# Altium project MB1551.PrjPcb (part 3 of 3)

## Sheet USB_TYPEC.SchDoc: USB TYPE C
size A3; Date: Not used; ApprovedBy: Not used; CheckedBy: Not used; Author: Not used; CompanyName: STMicroelectronics; DrawnBy: Not used; Engineer: Not used; Organization: Not used; Address1: Not used; Address2: Not used; Address3: Not used; Address4: Not used; DocumentNumber: 9; Revision: Not used; SheetNumber: 9; SheetTotal: 16
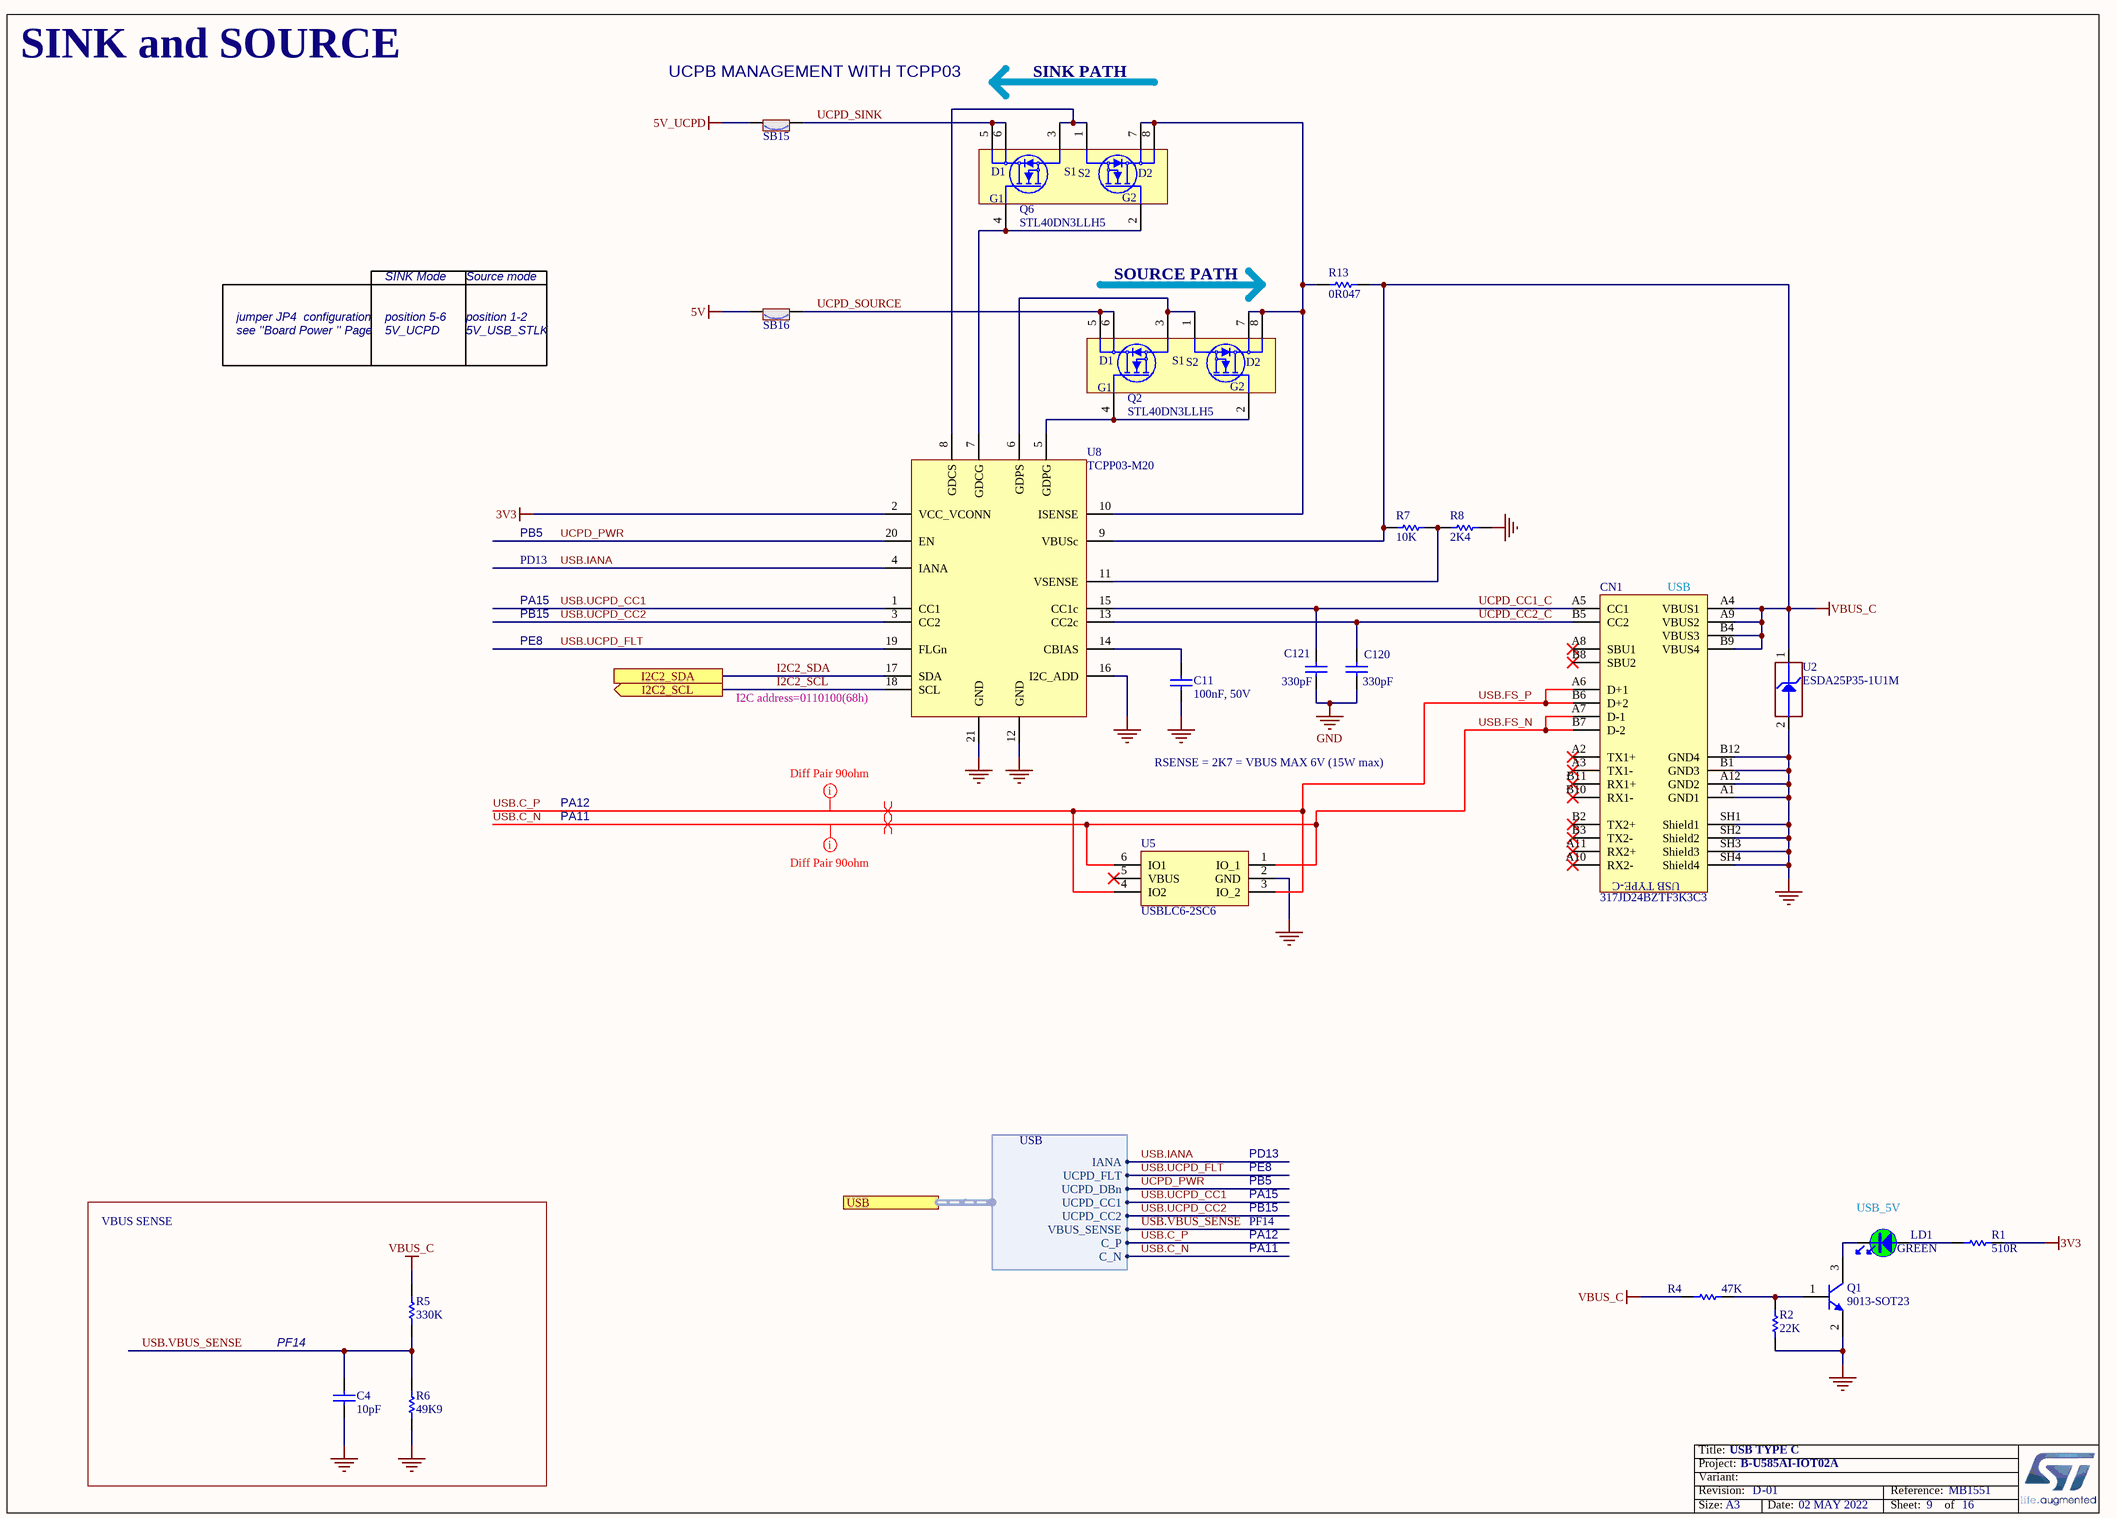
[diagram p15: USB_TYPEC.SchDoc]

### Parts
C4  value 10pF  [C0603]
C11  value 100nF, 50V  [C0603]
C120  value 330pF  [C0402]  (hidden comment: Capacitor)
C121  value 330pF  [C0402]  (hidden comment: Capacitor)
CN1  value 317JD24BZTF3K3C3  [CON_USB-TYPEC_COXOC_317JD24BZTF3K3C3]  (hidden comment: USB_TYPE_C_Receptacle_317JD24BZTF3K3C3)
LD1  value GREEN  [LED_0603_GREEN]
Q1  value 9013-SOT23  [NPN_SOT23]
Q2  STL40DN3LLH5  [PowerFLAT_5x6]
Q6  STL40DN3LLH5  [PowerFLAT_5x6]
R1  value 510R  [R0603]
R2  value 22K  [R0603]
R4  value 47K  [R0603]
R5  value 330K  [R0603]
R6  value 49K9  [R0603]
R7  value 10K  [R0603]
R8  value 2K4  [R0402]  (hidden comment: Resistor)
R13  value 0R047  [R0805_H0P5]  (hidden comment: Resistor)
SB15  (no value)  [SOLDER-BRIDGE_R0603-0R]
SB16  (no value)  [SOLDER-BRIDGE_R0603-0R]
U2  value ESDA25P35-1U1M  [ESD_QFN1610_2N_1K_2A]  (hidden comment: ESD-TRANSIL)
U5  USBLC6-2SC6  [ESD_SOT23-6L]
U8  TCPP03-M20  [ICC_QFN20-EPAD_4X4_P050]

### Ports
I2C2_SCL (out), I2C2_SDA, USB (harness USB)

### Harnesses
USB: UCPD_FLT, UCPD_DBn, UCPD_CC2, VBUS_SENSE, C_P, C_N, UCPD_CC1, IANA

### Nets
3V3: R1.1 U8.2(VCC_VCONN)
5V: SB16.2
5V_UCPD: SB15.2
GND: C4.1 C11.2 C120.1 C121.1 CN1.A1(GND1) CN1.A12(GND2) CN1.B1(GND3) CN1.B12(GND4) CN1.SH1(Shield1) CN1.SH2(Shield2) CN1.SH3(Shield3) CN1.SH4(Shield4) Q1.2(E) R2.1 R6.1 R8.2 U2.2(GND) U5.2(GND) U8.12(GND) U8.16(I2C_ADD) U8.21(GND)
VBUS_C: CN1.A4(VBUS1) CN1.A9(VBUS2) CN1.B4(VBUS3) CN1.B9(VBUS4) R4.1 R5.2 R7.2 R13.1 U2.1(IO1) U8.9(VBUSc)
I2C2_SCL: U8.18(SCL) ; port I2C2_SCL
I2C2_SDA: U8.17(SDA) ; port I2C2_SDA
UCPD_CC1_C: C121.2 CN1.A5(CC1) U8.15(CC1c)
UCPD_CC2_C: C120.2 CN1.B5(CC2) U8.13(CC2c)
UCPD_PWR: U8.20(EN) ; port USB.UCPD_DBn
UCPD_SINK: Q6.5(D1) Q6.6(D1) SB15.1
UCPD_SOURCE: Q2.5(D1) Q2.6(D1) SB16.1
USB.C_N: CN1.A7(D-1) CN1.B7(D-2) U5.1(IO_1) U5.6(IO1) ; port USB.C_N  [also labelled USB.FS_N]
USB.C_P: CN1.A6(D+1) CN1.B6(D+2) U5.3(IO_2) U5.4(IO2) ; port USB.C_P  [also labelled USB.FS_P]
USB.IANA: U8.4(IANA) ; port USB.IANA
USB.UCPD_CC1: U8.1(CC1) ; port USB.UCPD_CC1  [project net T.JTDI]
USB.UCPD_CC2: U8.3(CC2) ; port USB.UCPD_CC2
USB.UCPD_FLT: U8.19(FLGn) ; port USB.UCPD_FLT
USB.VBUS_SENSE: C4.2 R5.1 R6.2 ; port USB.VBUS_SENSE
NetC11_1: C11.1 U8.14(CBIAS)
NetLD1_1: LD1.1 R1.2
NetLD1_2: LD1.2 Q1.3(C)
NetQ1_1: Q1.1(B) R2.2 R4.2
NetQ2_1: Q2.1(S2) Q2.3(S1) U8.6(GDPS)
NetQ2_2: Q2.2(G2) Q2.4(G1) U8.5(GDPG)
NetQ2_7: Q2.7(D2) Q2.8(D2) Q6.7(D2) Q6.8(D2) R13.2 U8.10(ISENSE)
NetQ6_1: Q6.1(S2) Q6.3(S1) U8.8(GDCS)
NetQ6_2: Q6.2(G2) Q6.4(G1) U8.7(GDCG)
NetR7_1: R7.1 R8.1 U8.11(VSENSE)

Not connected (* = marked no-connect by the designer): CN1 A2(TX1+)* A3(TX1-)* A8(SBU1)* A10(RX2-)* A11(RX2+)* B2(TX2+)* B3(TX2-)* B8(SBU2)* B10(RX1-)* B11(RX1+)*; U5 5(VBUS)*

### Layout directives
mark named Diff Pair 90ohm: USB.C_N, USB.C_P
differential pair: USB.C_N, USB.C_P

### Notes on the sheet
- SINK and SOURCE
- (near SB15) UCPB MANAGEMENT WITH TCPP03
- SINK PATH
- jumper JP4  configuration
- position 5-6
- SINK Mode
- Source mode
- position 1-2
- SOURCE PATH
- see ''Board Power '' Page
- 5V_UCPD
- 5V_USB_STLK
- PB5
- PD13
- (near CN1) USB
- PA15
- PB15
- PE8
- (near U8) I2C address=0110100(68h)
- RSENSE = 2K7 = VBUS MAX 6V (15W max)
- PA12
- PA11
- VBUS SENSE
- PF14
- (near LD1) USB_5V

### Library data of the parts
C4 = MCD-00637: Capacitor, MLCC, 10pF, 50V, NPO, 5%, 0603, T=0,8mm; Manufacturer_Part_Number: CC0603JRNPO9BN100; Manufacturer: YAGEO; Provided_By: subcon; Initial_Board_Reference: MB1319
C11 = MCD-01099: Capacitor,100nF,50V,X7R,10%,0603; Manufacturer_Part_Number: CC0603KRX7R9BB104; Manufacturer: YAGEO; BMS_Part_Number: 9142278; Provided_By: SUBCO
C120 C121 = MCD-01579: Capacitor, MLCC, 330pF, 50V, NPO, +/-5%, 0402, T=0,5mm; Part_Preference: Recommended; Manufacturer: YAGEO; Manufacturer_Part_Number: CC0402JRNPO9BN331
CN1 = MCD-01108: USB tyce C certified receptacle for 1.6mm pcb height; Part_Type: Connector; Manufacturer: CHANT SINCERE (COXOC); Provided_By: SUBCO
LD1 = MCD-00050: LED, Green, 0603; Part_Type: Display; Manufacturer_Part_Number: 19-213SYGC/S530-E2/TR8; Manufacturer: EVERLIGHT; ECCN_US: EAR99; ECCN_EU: NEC; Provided_By: Subcon; Initial_Board_Reference: MB1274
Q1 = MCD-00073: NPN Bipolar Transistor; Part_Type: IC; Manufacturer_Part_Number: BSR14; Manufacturer: NXP; ECCN_US: EAR99; ECCN_EU: NEC; Provided_By: Subcon; Initial_Board_Reference: MB1274
Q2 Q6 = MCD-02152: Dual N-channel 30 V, 0.016 Ω typ., 40 A, STripFET™ H5 Power MOSFET; Part_Type: Transistor; Manufacturer: STMICROELECTRONICS; ECCN_US: EAR99; ECCN_EU: NEC; Provided_By: SUBCO
R1 = MCD-00225: Resistor,510R,0603,1%,1/10W; Manufacturer_Part_Number: RC0603FR-07510RL; Manufacturer: YAGEO; Provided_By: Subcon; Initial_Board_Reference: MB1319
R2 = MCD-00430: Resistor,22K,0603,1%,1/10W; Manufacturer_Part_Number: RC0603FR-0722KL; Manufacturer: YAGEO; Provided_By: Subcon
R4 = MCD-00222: Resistor,47K,0603,1%,1/10W; Manufacturer_Part_Number: RC0603FR-0747KL; Manufacturer: YAGEO; Provided_By: Subcon; Initial_Board_Reference: MB1319
R5 = MCD-00458: Resistor,330K,0603,1%,1/10W; Manufacturer_Part_Number: RC0603FR-07330KL; Manufacturer: YAGEO; Provided_By: Subcon
R6 = MCD-01171: Resistor,49K9,0603,1%; Manufacturer_Part_Number: RC0603FR-0749K9L; Manufacturer: YAGEO; Provided_By: Subcon; Initial_Board_Reference: MB1397
R7 = MCD-00220: Resistor,10K,0603,1%,1/10W; Manufacturer_Part_Number: RC0603FR-0710KL; Manufacturer: YAGEO; Provided_By: Subcon; Initial_Board_Reference: MB1319
R8 = MCD-00433: Resistor,2K4,0402,1%,1/16W; Part_Preference: Recommended; Manufacturer: YAGEO; Manufacturer_Part_Number: RC0402FR-072K4L
R13 = MCD-02151: Current Detection Resistor, 0R047, 0805, 1%, 1/4W; Manufacturer_Part_Number: RL0805FR-7W0R047L; Manufacturer: YAGEO; ECCN_US: NEC; ECCN_EU: EAR99; Provided_By: SUBCO
SB15 SB16 = MCD-00071: Solder Bridge ON; Part_Type: Mechanical; Provided_By: Subcon; Initial_Board_Reference: mb1274
U2 = MCD-01207: High power Transient voltage suppressor:25V/35A EOS and ESD transients protection.; Part_Type: Diode; Manufacturer: STMICROELECTRONICS; BMS_Part_Number: 9179045; ECCN_US: EAR99; ECCN_EU: NEC; Provided_By: SUBCO with ST control
U5 = MCD-00163: Very low capacitance ESD protection; Part_Type: IC; Manufacturer: STMICROELECTRONICS; BMS_Part_Number: 9151075; ECCN_US: EAR99; ECCN_EU: NEC; Provided_By: SUBCO with ST control
U8 = MCD-02130: USB Type-C Port Protection for USB DRP Power Delivery, PPS compliant; Part_Type: IC; Manufacturer: STMICROELECTRONICS; ECCN_US: EAR99; ECCN_EU: NEC; Provided_By: SUBCO with ST control

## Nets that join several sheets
2V8: BOARD_PWR (SB9.2 TP12.1), Camera (8 pins)
3V3: ARDUINO (CN17.2 CN17.4 R9.1), AUDIO (7 pins), BOARD_PWR (5 pins), Camera (R32.2), MCU_CLOCK_&_RESET (5 pins), MEMs (38 pins), OCTOSPI (SB2.1 SB8.1), STMod+ (8 pins), ST_LINK_V3E (CN9.3 CN10.1 R54.2), WIFI&BT (5 pins), USB_TYPEC (R1.1 U8.2)
5V: ARDUINO (CN17.5), BOARD_PWR (10 pins), STMod+ (CN2.6 CN2.15 CN3.6 CN3.15), ST_LINK_V3E (R57.1), USB_TYPEC (SB16.2)
5V_UCPD: BOARD_PWR (JP4.5), ST_LINK_V3E (D3.1), USB_TYPEC (SB15.2)
5V_USB_CHGR: BOARD_PWR (JP4.7), ST_LINK_V3E (8 pins)
5V_USB_STLK: BOARD_PWR (JP4.1), ST_LINK_V3E (C52.2 U18.1)
5V_VIN: ARDUINO (R63.2), BOARD_PWR (C116.2 JP4.3 U38.2 U38.4), ST_LINK_V3E (D2.1)
GND: ARDUINO (5 pins), AUDIO (7 pins), BOARD_PWR (13 pins), Camera (15 pins), MCU_CLOCK_&_RESET (14 pins), MCU_PWR (38 pins), Mechanical_Parts (H1.1 H3.1 H4.1), MEMs (42 pins), OCTOSPI (15 pins), STMod+ (10 pins), ST_LINK_V3E (101 pins), WIFI&BT (42 pins), USB_TYPEC (21 pins)
VDD_MCU: BOARD_PWR (JP3.1), MCU_IO (R27.1 R28.1 R59.1 R60.1), MCU_PWR (37 pins)
VIN: ARDUINO (CN17.8), BOARD_PWR (C117.2 U38.3)
VREFP: ARDUINO (C74.1 R47.2), MCU_PWR (C38.1 C39.2 R21.2 U13.L1)
ARD.D0_RX: ARDUINO (CN14.1), MCU_IO (U13.L13), STMod+ (U3.7)
ARD.D1_TX: ARDUINO (CN14.2), MCU_IO (U13.L12), STMod+ (U3.4)
ARD.D2_IO: ARDUINO (CN14.3), MCU_IO (U13.J11)
ARD.D3_TIM: ARDUINO (CN14.4), MCU_IO (U13.L5)
ARD.D4_INT: ARDUINO (CN14.5), MCU_IO (U13.L7)
ARD.D5_TIM: ARDUINO (CN14.6), MCU_IO (U13.D4)
ARD.D6_TIM: ARDUINO (CN14.7), MCU_IO (U13.B5)
ARD.D7_IO: ARDUINO (CN14.8), MCU_IO (U13.M6)
ARD.D8_IO: ARDUINO (CN13.1), MCU_IO (U13.J3)
ARD.D9_TIM: ARDUINO (CN13.2), MCU_IO (U13.G7)
ARD.D10_TIM_SPI1_NSS: ARDUINO (CN13.3), MCU_IO (U13.N8)
ARD.D11_TIM_SPI1_MOSI: ARDUINO (CN13.4), MCU_IO (U13.M9), STMod+ (U4.6)
ARD.D12_SPI1_MISO: ARDUINO (CN13.5), MCU_IO (U13.K8), STMod+ (U4.9)
ARD.D13_SPI1_SCK: ARDUINO (CN13.6 R48.1), MCU_IO (U13.L8), STMod+ (U4.14)
ARD_ADC.A0: ARDUINO (CN16.1), MCU_IO (U13.J2)
ARD_ADC.A1: ARDUINO (CN16.2), MCU_IO (U13.J4)
ARD_ADC.A2: ARDUINO (CN16.3), MCU_IO (U13.L4)
ARD_ADC.A3: ARDUINO (CN16.4), MCU_IO (U13.M4)
ARD_ADC.A4: ARDUINO (SB10.1), MCU_IO (U13.J5)
ARD_ADC.A5: ARDUINO (SB13.1), MCU_IO (U13.K5)
CAM.D0: Camera (CN7.23), MCU_IO (U13.H13)
CAM.D1: Camera (CN7.24), MCU_IO (U13.G12)
CAM.D2: Camera (CN7.25), MCU_IO (U13.G10)
CAM.D3: Camera (CN7.26), MCU_IO (U13.C4)
CAM.D4: Camera (CN7.27), MCU_IO (U13.C11)
CAM.D5: Camera (CN7.28), MCU_IO (U13.B10)
CAM.D6: Camera (CN7.29), MCU_IO (U13.A2)
CAM.D7: Camera (CN7.30), MCU_IO (U13.C3)
CAM.HSYNC: Camera (CN7.31), MCU_IO (U13.D12)
CAM.PIXCLK: Camera (CN7.33), MCU_IO (U13.N4)
CAM.PLUG: Camera (CN7.15 R32.1), MCU_IO (U13.A12)
CAM.RSTI: Camera (CN7.17), MCU_IO (U13.D11)
CAM.VSYNC: Camera (CN7.32), MCU_IO (U13.F5)
CAM.XSDN: Camera (CN7.19), MCU_IO (U13.D10)
I2C1_SCL: ARDUINO (CN13.10 SB12.1), Camera (Q5.3 R30.1), MCU_IO (R59.2 U13.E5), STMod+ (CN3.7)
I2C1_SDA: ARDUINO (CN13.9 SB11.1), Camera (Q4.3 R26.1), MCU_IO (R60.2 U13.D5), STMod+ (CN3.10)
I2C2_SCL: MCU_IO (R28.2 U13.E10), MEMs (8 pins), STMod+ (CN2.7), USB_TYPEC (U8.18)
I2C2_SDA: MCU_IO (R27.2 U13.F9), MEMs (8 pins), STMod+ (CN2.10), USB_TYPEC (U8.17)
LED_GREEN: MCU_CLOCK_&_RESET (R42.2), MCU_IO (U13.F8)
LED_RED: MCU_CLOCK_&_RESET (R41.2), MCU_IO (U13.E11)
Mems.INT_IIS2MDC: MCU_IO (U13.K11), MEMs (U25.7)
Mems.INT_LPS22HH: MCU_IO (U13.K13), MEMs (U26.7)
Mems.ISM330DLC_INT1: MCU_IO (U13.M8), MEMs (U21.4)
Mems.VL53_xshut: MCU_IO (SB4.2), MEMs (U27.A5)
Mems.VLX_GPIO: MCU_IO (U13.J9), MEMs (R43.1 SB17.2 U27.A3)
MIC.CCK0: AUDIO (U6.4), MCU_IO (U13.J7)
MIC.CCK1: AUDIO (U7.4), MCU_IO (U13.H4)
MIC.SDIN0: AUDIO (U7.1), MCU_IO (U13.N5)
MIC.SDINx: AUDIO (U6.1), MCU_IO (U13.H8)
NRST: ARDUINO (CN17.3), MCU_CLOCK_&_RESET (B2.1 B2.2 C42.2 U23.1), MCU_IO (U13.H3), OCTOSPI (R14.1 R38.1), ST_LINK_V3E (CN9.12 CN10.10 R22.1 U11.5)
OCTOSPI.F_CLK_P: MCU_IO (R67.2), OCTOSPI (U9.B2)
OCTOSPI.F_DQS: MCU_IO (U13.K6), OCTOSPI (U9.C3)
OCTOSPI.F_IO0: MCU_IO (U13.E2), OCTOSPI (U9.D3)
OCTOSPI.F_IO1: MCU_IO (U13.F3), OCTOSPI (U9.D2)
OCTOSPI.F_IO2: MCU_IO (U13.F4), OCTOSPI (U9.C4)
OCTOSPI.F_IO3: MCU_IO (U13.G5), OCTOSPI (U9.D4)
OCTOSPI.F_IO4: MCU_IO (U13.E9), OCTOSPI (U9.D5)
OCTOSPI.F_IO5: MCU_IO (U13.C13), OCTOSPI (U9.E3)
OCTOSPI.F_IO6: MCU_IO (U13.D9), OCTOSPI (U9.E2)
OCTOSPI.F_IO7: MCU_IO (U13.B13), OCTOSPI (U9.E1)
OCTOSPI.F_NCS: MCU_IO (R68.1), OCTOSPI (R12.1 U9.C2)
OCTOSPI.R_CLK_P: MCU_IO (R69.1), OCTOSPI (U20.B2 U37.6)
OCTOSPI.R_DQS: MCU_IO (U13.D3), OCTOSPI (U20.C3)
OCTOSPI.R_IO0: MCU_IO (U13.F1), OCTOSPI (U20.D3 U37.5)
OCTOSPI.R_IO1: MCU_IO (U13.G3), OCTOSPI (U20.D2 U37.2)
OCTOSPI.R_IO2: MCU_IO (U13.G2), OCTOSPI (U20.C4 U37.3)
OCTOSPI.R_IO3: MCU_IO (U13.H6), OCTOSPI (U20.D4 U37.7)
OCTOSPI.R_IO4: MCU_IO (U13.F10), OCTOSPI (U20.D5)
OCTOSPI.R_IO5: MCU_IO (U13.B12), OCTOSPI (U20.E3)
OCTOSPI.R_IO6: MCU_IO (U13.K1), OCTOSPI (U20.E2)
OCTOSPI.R_IO7: MCU_IO (U13.D7), OCTOSPI (U20.E1)
OCTOSPI.R_NCS: MCU_IO (R70.1), OCTOSPI (R37.1 U20.A3 U37.1)
PC14-OSC32_IN: MCU_CLOCK_&_RESET (C46.1 X2.2), MCU_IO (U13.D1)
PC15-OSC32_OUT: MCU_CLOCK_&_RESET (C45.1 X2.1), MCU_IO (U13.E1)
PH0-OSC_IN: MCU_CLOCK_&_RESET (C44.1 X1.1), MCU_IO (SB5.1 U13.H1)
PH1-OSC_OUT: MCU_CLOCK_&_RESET (C41.1 X1.3), MCU_IO (SB4.1 U13.J1)
PH3-BOOT0: MCU_CLOCK_&_RESET (R35.2), MCU_IO (U13.C5)
STMOD+.1_17: MCU_IO (U13.A1), STMod+ (CN3.17)
STMOD+.1_18: MCU_IO (U13.B9), STMod+ (CN3.18)
STMOD+.1_19: MCU_IO (U13.G4), STMod+ (CN3.19)
STMOD+.1_20: MCU_IO (U13.M12), STMod+ (CN3.20)
STMOD+.1_ADC: MCU_IO (U13.K4), STMod+ (CN3.13)
STMOD+.1_INT: MCU_IO (U13.C2), STMod+ (CN3.11 CN4.7)
STMOD+.1_RST: MCU_IO (U13.G8), STMod+ (CN3.12 CN4.8)
STMOD+.1_SPI1_MISO_alt1: MCU_IO (U13.J8), STMod+ (CN3.9)
STMOD+.1_SPI1_MOSI_alt1: MCU_IO (U13.H11), STMod+ (CN3.8)
STMOD+.1_SPI1_NSS: MCU_IO (U13.N1), STMod+ (U4.1)
STMOD+.1_TIM: MCU_IO (U13.D2), STMod+ (CN3.14)
STMOD+.1_UART2_CTS: MCU_IO (U13.K3), STMod+ (U4.15)
STMOD+.1_UART2_RTS: MCU_IO (U13.L3), STMod+ (U4.12)
STMOD+.1_UART2_RX: MCU_IO (U13.N2), STMod+ (U4.7)
STMOD+.1_UART2_TX: MCU_IO (U13.M2), STMod+ (U4.4)
STMOD+.2_17: MCU_IO (U13.H7), STMod+ (CN2.17)
STMOD+.2_18: MCU_IO (U13.F7), STMod+ (CN2.18)
STMOD+.2_19: MCU_IO (U13.E7), STMod+ (CN2.19)
STMOD+.2_20: MCU_IO (U13.H9), STMod+ (CN2.20)
STMOD+.2_ADC: MCU_IO (U13.J6), STMod+ (CN2.13)
STMOD+.2_INT: MCU_IO (U13.E4), STMod+ (CN2.11)
STMOD+.2_RST: MCU_IO (U13.N13), STMod+ (CN2.12)
STMOD+.2_SPI3_MISO: MCU_IO (U13.C7), STMod+ (U3.9)
STMOD+.2_SPI3_MISO_alt1: MCU_IO (U13.B6), STMod+ (CN2.9)
STMOD+.2_SPI3_MOSI: MCU_IO (U13.B7), STMod+ (U3.6)
STMOD+.2_SPI3_MOSI_alt1: MCU_IO (U13.E8), STMod+ (CN2.8)
STMOD+.2_SPI3_NSS: MCU_IO (U13.E6), STMod+ (U3.1)
STMOD+.2_SPI3_SCK: MCU_IO (U13.A7), STMod+ (U3.14)
STMOD+.2_TIM: MCU_IO (U13.G9), STMod+ (CN2.14)
STMOD+.2_UART3_CTS: MCU_IO (U13.M13), STMod+ (U3.15)
STMOD+.2_UART3_RTS: MCU_IO (U13.K10), STMod+ (U3.12)
STMOD+.UART2_SPI1_SEL: MCU_IO (U13.C12), STMod+ (R11.1 U4.3 U4.10)
STMOD+.UART3_SPI3_SEL: MCU_IO (U13.A13), STMod+ (R10.1 U3.3 U3.10)
STSAFE_EN: MCU_IO (U13.M5), MEMs (R71.1)
T.JTDI: MCU_IO (U13.A10), ST_LINK_V3E (CN9.10 CN10.8 U12.1), USB_TYPEC (U8.1)
T.MCO: MCU_IO (SB5.2), ST_LINK_V3E (C81.1 R49.2)
T.SWCLK: MCU_IO (U13.C10), ST_LINK_V3E (SW4.3)
T.SWCLK_B: ST_LINK_V3E (SW5.3), WIFI&BT (CN5.2 U1#2.26)
T.SWDIO: MCU_IO (U13.F12), ST_LINK_V3E (SW4.4)
T.SWDIO_B: ST_LINK_V3E (SW5.4), WIFI&BT (CN5.4 U1#2.25)
T.SWO: MCU_IO (U13.D6), ST_LINK_V3E (CN9.8 CN10.6 R20.1 U12.3)
T.VCP_RX: MCU_IO (U13.F11), ST_LINK_V3E (CN9.13 R19.2 U11.1)
T.VCP_TX: MCU_IO (U13.G11), ST_LINK_V3E (CN9.14 R18.1 U11.3)
UCPD_PWR: MCU_IO (U13.C6), USB_TYPEC (U8.20)
USB.C_N: MCU_IO (U13.G13), USB_TYPEC (CN1.A7 CN1.B7 U5.1 U5.6)
USB.C_P: MCU_IO (U13.F13), USB_TYPEC (CN1.A6 CN1.B6 U5.3 U5.4)
USB.IANA: MCU_IO (U13.K12), USB_TYPEC (U8.4)
USB.UCPD_CC2: MCU_IO (U13.L11), USB_TYPEC (U8.3)
USB.UCPD_FLT: MCU_IO (U13.K7), USB_TYPEC (U8.19)
USB.VBUS_SENSE: MCU_IO (U13.L6), USB_TYPEC (C4.2 R5.1 R6.2)
USER_BUTTON: MCU_CLOCK_&_RESET (C43.2 R39.1), MCU_IO (U13.E3)
WRLS.FLOW: MCU_IO (U13.A5), WIFI&BT (M1.13)
WRLS.NOTIFY: MCU_IO (U13.J10), WIFI&BT (M1.14)
WRLS.SPI2_MISO: MCU_IO (U13.D8), WIFI&BT (M1.7)
WRLS.SPI2_MOSI: MCU_IO (U13.C8), WIFI&BT (M1.9)
WRLS.SPI2_NSS: MCU_IO (U13.L10), WIFI&BT (M1.8)
WRLS.SPI2_SCK: MCU_IO (U13.F6), WIFI&BT (M1.10)
WRLS.UART4_RX: MCU_IO (U13.A9), WIFI&BT (U1#2.1)
WRLS.UART4_TX: MCU_IO (U13.C9), WIFI&BT (U1#2.56)
WRLS.WKUP_B: MCU_IO (U13.H10), WIFI&BT (U1#2.3)
WRLS.WKUP_W: MCU_IO (U13.N6), WIFI&BT (M1.11)

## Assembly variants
U585AI: not fitted C35 C36 C41 C44 C48 C88 CN5 CN6 CN10 CN11 CN15 H1 H3 H4 HW3 HW4 JP1 R10 R11 R12 R15 R26 R30 R37 R47 R49 SB5 SB7 SB11 SB12 U37 X1
U585AI1: not fitted C35 C36 C41 C44 C48 C88 CN5 CN6 CN10 CN11 CN15 H1 H3 H4 HW3 HW4 JP1 R10 R11 R12 R15 R26 R30 R37 R47 R49 SB5 SB7 SB11 SB12 U37 X1; alternate parts U17 -> MCD-03497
